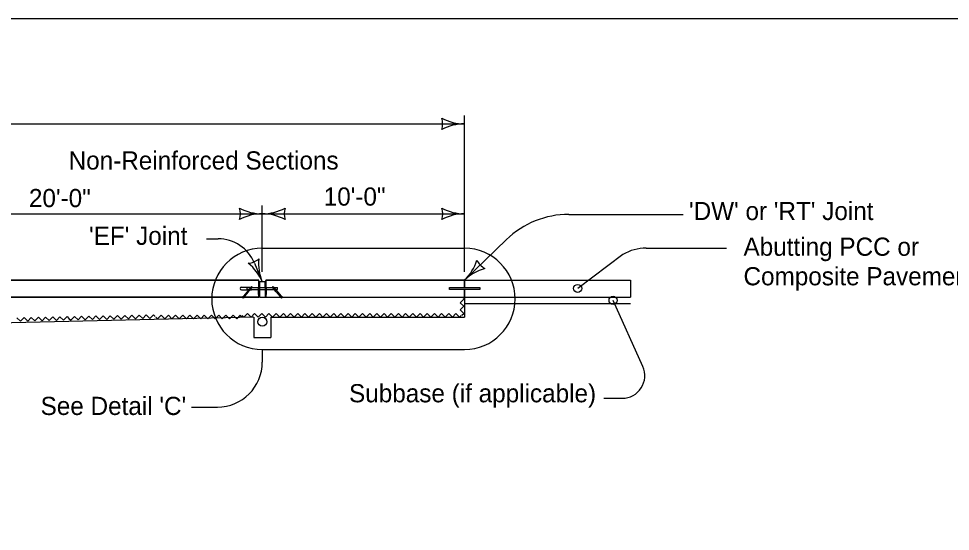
# Model space of a CAD drawing. Extents: x -2135039 to -2124495, y -2139046 to -2132546.
# Drawn here: x -2130034 to -2129213, y -2133467 to -2133016 of the extents above; entities that cross this region are included whole.
import ezdxf

# ---------------------------------------------------------------- set-up
doc = ezdxf.new("R2010")
doc.units = 0
for name, color, linetype in [('BridgeSuperStructureExisting', 7, 'Continuous'), ('dsnAlignmentStation', 7, 'Continuous'), ('dsnCellElements', 7, 'Continuous'), ('dsnStdLabel', 7, 'Continuous'), ('TC_Barrier', 7, 'Continuous')]:
    doc.layers.add(name, color=color, linetype=linetype)

msp = doc.modelspace()

# ---------------------------------------------------------------- linework, layer by layer
at = {"layer": 'BridgeSuperStructureExisting'}
for p, q in [((-2129826.16, -2133231.17), (-2129819.23, -2133247.83)), ((-2130977.53, -2133246.22), (-2129822.62, -2133246.22)), ((-2129822.62, -2133246.22), (-2130175.63, -2133246.22)), ((-2129822.2, -2133252.74), (-2129822.2, -2133246.64)), ((-2129822.2, -2133256.56), (-2129822.2, -2133246.64)), ((-2129816.26, -2133246.64), (-2129816.26, -2133252.76)), ((-2129816.26, -2133256.56), (-2129816.26, -2133246.64)), ((-2129815.85, -2133246.22), (-2129641.03, -2133246.22)), ((-2129641.03, -2133246.22), (-2129815.84, -2133246.22)), ((-2129641.03, -2133252.72), (-2129641.03, -2133246.22)), ((-2129641.03, -2133246.22), (-2129641.03, -2133252.72)), ((-2129641.03, -2133246.22), (-2129494.85, -2133246.22)), ((-2129499.01, -2133246.69), (-2129499.01, -2133246.69)), ((-2129494.85, -2133246.22), (-2129494.85, -2133261.07)), ((-2129837.64, -2133252.46), (-2129829.08, -2133252.46)), ((-2129837.64, -2133254.84), (-2129831.07, -2133254.84)), ((-2129832.6, -2133254.54), (-2129832.6, -2133252.76)), ((-2129832.6, -2133252.76), (-2129829.33, -2133252.76)), ((-2129832.6, -2133254.54), (-2129830.82, -2133254.54)), ((-2129828.84, -2133252.17), (-2129832.52, -2133256.56)), ((-2129831.59, -2133256.56), (-2129828.29, -2133252.63)), ((-2129830.14, -2133254.84), (-2129828.73, -2133254.84)), ((-2129829.89, -2133254.54), (-2129822.56, -2133254.54)), ((-2129829.33, -2133252.76), (-2129829.33, -2133252.76)), ((-2129828.73, -2133254.54), (-2129828.73, -2133254.84)), ((-2129828.4, -2133252.76), (-2129822.56, -2133252.76)), ((-2129822.56, -2133258.7), (-2129822.56, -2133252.76)), ((-2129822.56, -2133258.7), (-2129822.56, -2133252.76)), ((-2129822.38, -2133252.58), (-2129822.38, -2133252.58)), ((-2129822.2, -2133247.83), (-2129821.61, -2133247.83)), ((-2129822.14, -2133247.83), (-2129822.14, -2133256.56)), ((-2129822.08, -2133247.83), (-2129822.08, -2133256.56)), ((-2129822.03, -2133247.83), (-2129822.03, -2133256.56)), ((-2129821.96, -2133247.83), (-2129821.96, -2133256.56)), ((-2129821.91, -2133247.83), (-2129821.91, -2133256.56)), ((-2129821.84, -2133247.83), (-2129821.84, -2133256.56)), ((-2129821.79, -2133247.83), (-2129821.79, -2133256.56)), ((-2129821.72, -2133247.83), (-2129821.72, -2133256.56)), ((-2129821.67, -2133247.83), (-2129821.67, -2133256.56)), ((-2129821.61, -2133247.83), (-2129821.61, -2133252.76)), ((-2129816.85, -2133247.83), (-2129821.61, -2133247.83)), ((-2129821.61, -2133247.83), (-2129821.61, -2133252.76)), ((-2129821.61, -2133252.76), (-2129821.61, -2133254.54)), ((-2129821.61, -2133252.76), (-2129816.85, -2133252.76)), ((-2129821.61, -2133254.54), (-2129816.85, -2133254.54)), ((-2129821.61, -2133254.54), (-2129821.61, -2133256.56)), ((-2129816.85, -2133247.83), (-2129816.85, -2133252.76)), ((-2129816.85, -2133252.76), (-2129816.85, -2133247.83)), ((-2129816.85, -2133247.83), (-2129816.26, -2133247.83)), ((-2129816.85, -2133252.76), (-2129816.85, -2133254.54)), ((-2129816.85, -2133254.54), (-2129816.85, -2133256.56)), ((-2129816.8, -2133247.83), (-2129816.8, -2133256.56)), ((-2129816.73, -2133247.83), (-2129816.73, -2133256.56)), ((-2129816.68, -2133247.83), (-2129816.68, -2133256.56)), ((-2129816.62, -2133247.83), (-2129816.62, -2133256.56)), ((-2129816.56, -2133247.83), (-2129816.56, -2133256.56)), ((-2129816.5, -2133247.83), (-2129816.5, -2133256.56)), ((-2129816.44, -2133247.83), (-2129816.44, -2133256.56)), ((-2129816.38, -2133247.83), (-2129816.38, -2133256.56)), ((-2129816.32, -2133247.83), (-2129816.32, -2133256.56)), ((-2129815.9, -2133252.76), (-2129815.9, -2133258.7)), ((-2129815.9, -2133258.7), (-2129815.9, -2133252.76)), ((-2129815.9, -2133252.76), (-2129810.07, -2133252.76)), ((-2129815.9, -2133253), (-2129815.9, -2133253)), ((-2129815.9, -2133254.54), (-2129808.57, -2133254.54)), ((-2129806.87, -2133256.56), (-2129810.17, -2133252.63)), ((-2129809.62, -2133252.17), (-2129805.94, -2133256.56)), ((-2129809.13, -2133252.76), (-2129809.13, -2133252.76)), ((-2129809.13, -2133252.76), (-2129805.87, -2133252.76)), ((-2129807.64, -2133254.54), (-2129805.87, -2133254.54)), ((-2129805.87, -2133254.54), (-2129805.87, -2133252.76)), ((-2129654.4, -2133254.58), (-2129654.4, -2133252.72)), ((-2129654.4, -2133252.72), (-2129641.03, -2133252.72)), ((-2129654.4, -2133254.58), (-2129654.4, -2133252.72)), ((-2129654.4, -2133252.72), (-2129627.67, -2133252.72)), ((-2129641.03, -2133254.58), (-2129654.4, -2133254.58)), ((-2129627.67, -2133254.58), (-2129654.4, -2133254.58)), ((-2129641.03, -2133261.07), (-2129641.03, -2133254.58)), ((-2129641.03, -2133254.58), (-2129641.03, -2133261.07)), ((-2129627.67, -2133252.72), (-2129627.67, -2133254.58)), ((-2129836.3, -2133261.07), (-2130977.53, -2133261.07)), ((-2130175.63, -2133261.07), (-2129836.31, -2133261.07)), ((-2129834.27, -2133258.65), (-2129836.69, -2133261.53)), ((-2129836.14, -2133261.99), (-2129836.69, -2133261.53)), ((-2129836.31, -2133261.07), (-2129822.2, -2133261.07)), ((-2129822.2, -2133261.07), (-2129836.31, -2133261.07)), ((-2129833.34, -2133258.65), (-2129836.14, -2133261.99)), ((-2129832.52, -2133256.56), (-2129834.27, -2133258.65)), ((-2129831.59, -2133256.56), (-2129833.34, -2133258.65)), ((-2129822.56, -2133258.7), (-2129822.56, -2133258.7)), ((-2129822.2, -2133258.65), (-2129822.2, -2133256.56)), ((-2129822.2, -2133261.07), (-2129822.2, -2133258.65)), ((-2129822.2, -2133261.07), (-2129822.2, -2133258.7)), ((-2129822.14, -2133256.56), (-2129822.14, -2133258.65)), ((-2129822.14, -2133258.65), (-2129822.14, -2133261.07)), ((-2129822.08, -2133256.56), (-2129822.08, -2133258.65)), ((-2129822.08, -2133258.65), (-2129822.08, -2133261.07)), ((-2129822.03, -2133256.56), (-2129822.03, -2133258.65)), ((-2129822.03, -2133258.65), (-2129822.03, -2133261.07)), ((-2129821.96, -2133256.56), (-2129821.96, -2133258.65)), ((-2129821.96, -2133258.65), (-2129821.96, -2133261.07)), ((-2129821.91, -2133256.56), (-2129821.91, -2133258.65)), ((-2129821.91, -2133258.65), (-2129821.91, -2133261.07)), ((-2129821.84, -2133256.56), (-2129821.84, -2133258.65)), ((-2129821.84, -2133258.65), (-2129821.84, -2133261.07)), ((-2129821.79, -2133256.56), (-2129821.79, -2133258.65)), ((-2129821.79, -2133258.65), (-2129821.79, -2133261.07)), ((-2129821.72, -2133256.56), (-2129821.72, -2133258.65)), ((-2129821.72, -2133258.65), (-2129821.72, -2133261.07)), ((-2129821.67, -2133256.56), (-2129821.67, -2133258.65)), ((-2129821.67, -2133258.65), (-2129821.67, -2133261.07)), ((-2129821.61, -2133256.56), (-2129821.61, -2133258.65)), ((-2129821.61, -2133258.65), (-2129821.61, -2133261.07)), ((-2129821.61, -2133261.07), (-2129816.85, -2133261.07)), ((-2129816.85, -2133256.56), (-2129816.85, -2133258.65)), ((-2129816.85, -2133258.65), (-2129816.85, -2133261.07)), ((-2129816.85, -2133261.07), (-2129641.03, -2133261.07)), ((-2129816.8, -2133256.56), (-2129816.8, -2133258.65)), ((-2129816.8, -2133258.65), (-2129816.8, -2133261.07)), ((-2129816.73, -2133256.56), (-2129816.73, -2133258.65)), ((-2129816.73, -2133258.65), (-2129816.73, -2133261.07)), ((-2129816.68, -2133256.56), (-2129816.68, -2133258.65)), ((-2129816.68, -2133258.65), (-2129816.68, -2133261.07)), ((-2129816.62, -2133256.56), (-2129816.62, -2133258.65)), ((-2129816.62, -2133258.65), (-2129816.62, -2133261.07)), ((-2129816.56, -2133256.56), (-2129816.56, -2133258.65)), ((-2129816.56, -2133258.65), (-2129816.56, -2133261.07)), ((-2129816.5, -2133256.56), (-2129816.5, -2133258.65)), ((-2129816.5, -2133258.65), (-2129816.5, -2133261.07)), ((-2129816.44, -2133256.56), (-2129816.44, -2133258.65)), ((-2129816.44, -2133258.65), (-2129816.44, -2133261.07)), ((-2129816.38, -2133256.56), (-2129816.38, -2133258.65)), ((-2129816.38, -2133258.65), (-2129816.38, -2133261.07)), ((-2129816.32, -2133256.56), (-2129816.32, -2133258.65)), ((-2129816.32, -2133258.65), (-2129816.32, -2133261.07)), ((-2129816.26, -2133258.65), (-2129816.26, -2133256.56)), ((-2129816.26, -2133261.07), (-2129816.26, -2133258.65)), ((-2129816.26, -2133258.7), (-2129816.26, -2133261.07)), ((-2129816.26, -2133261.07), (-2129641.03, -2133261.07)), ((-2129806.87, -2133256.56), (-2129805.12, -2133258.65)), ((-2129805.94, -2133256.56), (-2129804.19, -2133258.65)), ((-2129805.12, -2133258.65), (-2129802.32, -2133261.99)), ((-2129804.19, -2133258.65), (-2129801.77, -2133261.53)), ((-2129802.32, -2133261.99), (-2129801.77, -2133261.53)), ((-2129641.03, -2133261.07), (-2129641.03, -2133278.89)), ((-2129641.03, -2133261.07), (-2129494.85, -2133261.07)), ((-2129494.85, -2133267.01), (-2129641.03, -2133267.01)), ((-2129826.66, -2133278.89), (-2130943.89, -2133304.14)), ((-2129826.66, -2133278.89), (-2129826.66, -2133296.71)), ((-2129811.81, -2133278.89), (-2129641.03, -2133278.89)), ((-2129811.81, -2133278.89), (-2129811.81, -2133296.71)), ((-2129826.66, -2133296.71), (-2129811.81, -2133296.71))]:
    msp.add_line(p, q, dxfattribs=at)
for points in [[(-2129821.61, -2133247.88), (-2129821.56, -2133247.83)], [(-2129821.61, -2133254.64), (-2129821.51, -2133254.54)], [(-2129816.26, -2133252.76), (-2129816.26, -2133252.76)], [(-2129643.34, -2133277.18), (-2129641.76, -2133275.6), (-2129644.93, -2133272.43), (-2129641.76, -2133269.26), (-2129644.93, -2133266.1), (-2129641.76, -2133262.93), (-2129642.2, -2133262.49)], [(-2130035.49, -2133279.25), (-2130032.26, -2133282.35), (-2130029.16, -2133279.12), (-2130025.92, -2133282.21), (-2130022.82, -2133278.98), (-2130019.59, -2133282.08), (-2130016.49, -2133278.84), (-2130013.25, -2133281.94), (-2130010.15, -2133278.71), (-2130006.92, -2133281.81), (-2130003.82, -2133278.57), (-2130000.58, -2133281.67), (-2129997.49, -2133278.43), (-2129994.25, -2133281.54), (-2129991.15, -2133278.3), (-2129989.53, -2133279.85)], [(-2129989.53, -2133279.85), (-2129987.92, -2133281.4), (-2129984.81, -2133278.17), (-2129981.58, -2133281.27), (-2129978.48, -2133278.03), (-2129975.25, -2133281.13), (-2129972.15, -2133277.9), (-2129968.91, -2133280.99), (-2129965.81, -2133277.76), (-2129962.58, -2133280.86), (-2129959.48, -2133277.62), (-2129956.25, -2133280.72), (-2129953.14, -2133277.49), (-2129949.91, -2133280.59), (-2129946.81, -2133277.35), (-2129943.57, -2133280.45), (-2129940.47, -2133277.22), (-2129937.24, -2133280.32), (-2129934.14, -2133277.08), (-2129930.9, -2133280.18), (-2129927.8, -2133276.95), (-2129924.57, -2133280.05), (-2129921.47, -2133276.81), (-2129918.24, -2133279.91), (-2129915.13, -2133276.68), (-2129913.52, -2133278.23)], [(-2129913.07, -2133278.69), (-2129911.48, -2133280.27), (-2129908.31, -2133277.11), (-2129905.14, -2133280.27), (-2129901.98, -2133277.09), (-2129898.81, -2133280.26), (-2129895.64, -2133277.09), (-2129892.47, -2133280.25), (-2129889.31, -2133277.08), (-2129886.13, -2133280.24), (-2129882.97, -2133277.07), (-2129879.8, -2133280.23), (-2129876.63, -2133277.06), (-2129873.46, -2133280.23), (-2129870.3, -2133277.05), (-2129867.13, -2133280.22), (-2129863.96, -2133277.05), (-2129860.79, -2133280.21), (-2129857.63, -2133277.04), (-2129854.45, -2133280.2), (-2129851.29, -2133277.03), (-2129848.12, -2133280.19), (-2129844.95, -2133277.02), (-2129841.78, -2133280.19), (-2129838.62, -2133277.01), (-2129837.03, -2133278.59)], [(-2129837.09, -2133277.2), (-2129835.51, -2133278.78), (-2129832.34, -2133275.62), (-2129829.17, -2133278.78), (-2129826, -2133275.62), (-2129822.83, -2133278.78), (-2129819.67, -2133275.61), (-2129816.5, -2133278.78), (-2129813.33, -2133275.61), (-2129810.16, -2133278.78), (-2129806.99, -2133275.61), (-2129803.83, -2133278.78), (-2129800.66, -2133275.6), (-2129797.49, -2133278.77), (-2129794.32, -2133275.6), (-2129791.15, -2133278.77), (-2129787.99, -2133275.6), (-2129784.82, -2133278.77), (-2129781.65, -2133275.6), (-2129778.48, -2133278.76), (-2129775.31, -2133275.59), (-2129772.15, -2133278.76), (-2129768.98, -2133275.59), (-2129765.81, -2133278.76), (-2129762.64, -2133275.59), (-2129761.06, -2133277.17)], [(-2129761.06, -2133277.17), (-2129759.47, -2133278.76), (-2129756.31, -2133275.58), (-2129753.14, -2133278.75), (-2129749.97, -2133275.58), (-2129746.8, -2133278.75), (-2129743.63, -2133275.58), (-2129740.47, -2133278.75), (-2129737.3, -2133275.58), (-2129734.13, -2133278.74), (-2129730.96, -2133275.58), (-2129727.79, -2133278.74), (-2129724.63, -2133275.58), (-2129721.46, -2133278.74), (-2129718.29, -2133275.57), (-2129715.12, -2133278.74), (-2129711.95, -2133275.57), (-2129708.79, -2133278.74), (-2129705.62, -2133275.57), (-2129702.45, -2133278.74), (-2129699.28, -2133275.56), (-2129696.11, -2133278.73), (-2129692.95, -2133275.56), (-2129689.78, -2133278.73), (-2129686.61, -2133275.56), (-2129685.03, -2133277.14)], [(-2129685.03, -2133277.14), (-2129683.44, -2133278.73), (-2129680.27, -2133275.56), (-2129677.11, -2133278.72), (-2129673.94, -2133275.55), (-2129670.77, -2133278.72), (-2129667.6, -2133275.55), (-2129664.43, -2133278.72), (-2129661.27, -2133275.55), (-2129658.1, -2133278.72), (-2129654.93, -2133275.54), (-2129651.76, -2133278.71), (-2129648.59, -2133275.54), (-2129645.43, -2133278.71), (-2129644.06, -2133277.34)]]:
    msp.add_lwpolyline(points, dxfattribs=at)
for centre, radius in [((-2129831.58, -2133255.07), 0.238), ((-2129807.13, -2133254.78), 0.238), ((-2129836.42, -2133260.84), 0.238), ((-2129802.04, -2133260.84), 0.238), ((-2129819.23, -2133282.85), 3.96)]:
    msp.add_circle(centre, radius, dxfattribs=at)
for centre, radius, start, end in [((-2129676.87, -2133108.6), 16.51, 342.26665, 17.73335), ((-2129641.03, -2133065.85), 42.75, 241.92751, 270), ((-2129676.87, -2133108.6), 16.51, 342.26665, 17.73335), ((-2129641.03, -2133065.85), 42.75, 241.92751, 270), ((-2129641.03, -2133151.34), 42.75, 90, 118.07249), ((-2129641.03, -2133151.34), 42.75, 90, 118.07249), ((-2129822.62, -2133246.64), 0.416, 360, 90), ((-2129822.61, -2133246.64), 0.416, 0, 90), ((-2129815.84, -2133246.64), 0.416, 90, 180), ((-2129815.84, -2133246.64), 0.416, 90, 180), ((-2129837.64, -2133253.65), 1.19, 90, 270), ((-2129828.56, -2133252.4), 0.356, 320.00367, 139.99636), ((-2129822.38, -2133252.76), 0.178, 5.43269, 180), ((-2129822.38, -2133252.76), 0.178, 0, 180), ((-2129822.38, -2133252.76), 0.178, 0, 180), ((-2129816.08, -2133252.76), 0.178, 0, 180), ((-2129816.08, -2133252.76), 0.178, 0, 180), ((-2129809.89, -2133252.4), 0.356, 40.00364, 219.99633), ((-2129822.38, -2133258.7), 0.178, 180, 359.93724), ((-2129822.38, -2133258.7), 0.178, 180, 0), ((-2129816.08, -2133258.7), 0.178, 180, 0), ((-2129816.08, -2133258.7), 0.178, 180, 0)]:
    msp.add_arc(centre, radius, start, end, dxfattribs=at)
for points in [[(-2129815.9, -2133252.88), (-2129815.87, -2133252.88), (-2129815.84, -2133252.88), (-2129815.82, -2133252.88), (-2129815.8, -2133252.88), (-2129815.78, -2133252.88), (-2129815.76, -2133252.88)], [(-2129815.9, -2133253), (-2129815.87, -2133253), (-2129815.84, -2133253), (-2129815.82, -2133253), (-2129815.8, -2133253), (-2129815.78, -2133253), (-2129815.76, -2133253)], [(-2129815.9, -2133253.12), (-2129815.87, -2133253.12), (-2129815.84, -2133253.12), (-2129815.82, -2133253.12), (-2129815.8, -2133253.12), (-2129815.78, -2133253.12), (-2129815.76, -2133253.12)], [(-2129815.9, -2133253.23), (-2129815.87, -2133253.24), (-2129815.84, -2133253.23), (-2129815.82, -2133253.23), (-2129815.8, -2133253.23), (-2129815.78, -2133253.24), (-2129815.76, -2133253.23)], [(-2129815.9, -2133253.35), (-2129815.87, -2133253.36), (-2129815.84, -2133253.35), (-2129815.82, -2133253.35), (-2129815.8, -2133253.35), (-2129815.78, -2133253.36), (-2129815.76, -2133253.35)], [(-2129815.9, -2133253.47), (-2129815.87, -2133253.48), (-2129815.84, -2133253.47), (-2129815.82, -2133253.47), (-2129815.8, -2133253.47), (-2129815.78, -2133253.48), (-2129815.76, -2133253.47)], [(-2129815.9, -2133253.59), (-2129815.87, -2133253.59), (-2129815.84, -2133253.59), (-2129815.82, -2133253.59), (-2129815.8, -2133253.59), (-2129815.78, -2133253.59), (-2129815.76, -2133253.59)], [(-2129815.9, -2133253.71), (-2129815.87, -2133253.71), (-2129815.84, -2133253.71), (-2129815.82, -2133253.71), (-2129815.8, -2133253.71), (-2129815.78, -2133253.71), (-2129815.76, -2133253.71)], [(-2129815.9, -2133253.83), (-2129815.87, -2133253.83), (-2129815.84, -2133253.83), (-2129815.82, -2133253.83), (-2129815.8, -2133253.83), (-2129815.78, -2133253.83), (-2129815.76, -2133253.83)], [(-2129815.9, -2133253.95), (-2129815.87, -2133253.95), (-2129815.84, -2133253.95), (-2129815.82, -2133253.95), (-2129815.8, -2133253.95), (-2129815.78, -2133253.95), (-2129815.76, -2133253.95)], [(-2129815.9, -2133254.07), (-2129815.87, -2133254.07), (-2129815.84, -2133254.07), (-2129815.82, -2133254.07), (-2129815.8, -2133254.07), (-2129815.78, -2133254.07), (-2129815.76, -2133254.07)], [(-2129815.9, -2133254.18), (-2129815.87, -2133254.19), (-2129815.84, -2133254.18), (-2129815.82, -2133254.18), (-2129815.8, -2133254.18), (-2129815.78, -2133254.19), (-2129815.76, -2133254.18)], [(-2129815.9, -2133254.3), (-2129815.87, -2133254.31), (-2129815.84, -2133254.3), (-2129815.82, -2133254.3), (-2129815.8, -2133254.3), (-2129815.78, -2133254.31), (-2129815.76, -2133254.3)], [(-2129815.9, -2133254.42), (-2129815.87, -2133254.43), (-2129815.84, -2133254.42), (-2129815.82, -2133254.42), (-2129815.8, -2133254.42), (-2129815.78, -2133254.43), (-2129815.76, -2133254.42)]]:
    msp.add_spline(points, degree=3, dxfattribs=at)
at = {"layer": 'dsnAlignmentStation'}
msp.add_lwpolyline([(-2131334.44, -2133015.96), (-2128199.45, -2133015.96), (-2128199.45, -2135025.95), (-2131334.44, -2135025.95)], close=True, dxfattribs=at)
at = {"layer": 'dsnCellElements'}
for centre, radius, start, end in [((-2129854.87, -2133187.8), 16.42, 342.26665, 17.73335), ((-2129819.23, -2133145.3), 42.5, 241.92751, 270), ((-2129819.23, -2133230.3), 42.5, 90, 118.07249), ((-2129819.23, -2133145.3), 42.5, 270, 298.07249), ((-2129819.23, -2133230.3), 42.5, 61.92751, 90), ((-2129783.59, -2133187.8), 16.42, 162.26665, 197.73335), ((-2129676.67, -2133187.8), 16.42, 342.26665, 17.73335), ((-2129641.03, -2133145.3), 42.5, 241.92751, 270), ((-2129641.03, -2133230.3), 42.5, 90, 118.07249), ((-2129832.92, -2133214.93), 16.42, 274.86526, 310.33197), ((-2129779.99, -2133231.5), 42.5, 174.52613, 202.59862), ((-2129670.58, -2133215.68), 42.5, 314.0496, 342.12209), ((-2129615.42, -2133221.45), 16.42, 206.31625, 241.78295), ((-2129858.47, -2133264.16), 42.5, 22.59862, 50.6711), ((-2129611.48, -2133276.77), 42.5, 105.97712, 134.0496)]:
    msp.add_arc(centre, radius, start, end, dxfattribs=at)
at = {"layer": 'dsnStdLabel'}
for p, q in [((-2129641.03, -2133238.8), (-2129641.03, -2133101.17)), ((-2130980.5, -2133108.6), (-2129641.03, -2133108.6)), ((-2129819.23, -2133238.8), (-2129819.23, -2133180.37)), ((-2130175.63, -2133187.8), (-2129819.23, -2133187.8)), ((-2129819.23, -2133187.8), (-2129641.03, -2133187.8)), ((-2129549.07, -2133188.26), (-2129448.38, -2133188.26)), ((-2129868.5, -2133209.83), (-2129858.16, -2133209.83)), ((-2129641.03, -2133246.22), (-2129604.14, -2133210.54)), ((-2129819.23, -2133218.13), (-2129641.03, -2133218.13)), ((-2129480.96, -2133217.97), (-2129410.35, -2133217.97)), ((-2129501.53, -2133223.72), (-2129541.39, -2133253.49)), ((-2129484, -2133322.29), (-2129510.24, -2133263.99)), ((-2129819.23, -2133307.23), (-2129819.23, -2133318.33)), ((-2129819.23, -2133307.23), (-2129641.03, -2133307.23)), ((-2129518.28, -2133350.21), (-2129502.05, -2133350.21)), ((-2129881.47, -2133357.93), (-2129858.83, -2133357.93))]:
    msp.add_line(p, q, dxfattribs=at)
for centre, radius, start, end in [((-2129549.07, -2133267.46), 79.2, 90, 134.04978), ((-2129858.15, -2133244.48), 34.65, 22.59071, 90), ((-2129819.23, -2133262.68), 44.55, 90, 270), ((-2129641.03, -2133262.68), 44.55, 270, 90), ((-2129480.96, -2133257.56), 39.6, 90, 121.29536), ((-2129858.83, -2133318.33), 39.6, 270, 360), ((-2129502.05, -2133330.41), 19.8, 270, 24.23803)]:
    msp.add_arc(centre, radius, start, end, dxfattribs=at)
at = {"layer": 'TC_Barrier'}
for centre in [(-2129541.39, -2133253.49), (-2129510.24, -2133263.99)]:
    msp.add_circle(centre, 3.54, dxfattribs=at)

# ---------------------------------------------------------------- texts
at = {"layer": 'dsnStdLabel'}
for s, p in [('Non-Reinforced Sections', (-2129989.86, -2133148.8)), ('10\'-0"', (-2129765.13, -2133180.59)), ('20\'-0"', (-2130024.83, -2133181.92)), ("'DW' or 'RT' Joint", (-2129443.32, -2133193.29)), ("'EF' Joint", (-2129971.85, -2133215.17)), ('Abutting PCC or', (-2129395.29, -2133224.75)), ('Composite Pavement', (-2129395.29, -2133250.75)), ('Subbase (if applicable)', (-2129742.8, -2133353.77)), ("See Detail 'C'", (-2130014.55, -2133364.94))]:
    msp.add_text(s, height=16, dxfattribs=at).set_placement(p)

doc.saveas('drawing.dxf')
